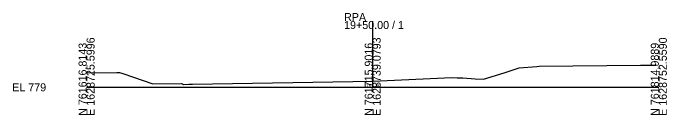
# Model space of a CAD drawing. Extents: x -26 to 203, y 990 to 7517.
# Drawn here: x -25.7 to 202.8, y 2990.3 to 3026 of the extents above; entities that cross this region are included whole.
import ezdxf

# ---------------------------------------------------------------- set-up
doc = ezdxf.new("R2010")
doc.units = 0
for name, color, linetype in [('Exist Cross Section Cell', 7, 'Continuous'), ('Exist XS Center Line Elevation Label', 7, 'Continuous'), ('Exist XS Ground Line', 7, 'Continuous')]:
    doc.layers.add(name, color=color, linetype=linetype)

msp = doc.modelspace()

# ---------------------------------------------------------------- linework, layer by layer
at = {"layer": 'Exist Cross Section Cell'}
for p, q in [((100, 3000), (100, 3023.24)), ((0, 3000), (100, 3000)), ((100, 3000), (200, 3000))]:
    msp.add_line(p, q, dxfattribs=at)
at = {"layer": 'Exist XS Ground Line'}
for p, q in [((158.14, 3007.41), (193.61, 3007.75)), ((193.61, 3007.75), (199.01, 3007.74)), ((199.01, 3007.74), (199.21, 3007.72)), ((145.96, 3005.04), (151.14, 3006.86)), ((151.14, 3006.86), (157.38, 3007.28)), ((157.38, 3007.28), (158.14, 3007.41)), ((0, 3005.12), (10.57, 3005.17)), ((10.57, 3005.17), (11.04, 3005.18)), ((11.04, 3005.18), (11.46, 3005.19)), ((11.46, 3005.19), (12.71, 3004.83)), ((12.71, 3004.83), (23.15, 3001.27)), ((100, 3002.2), (127.67, 3003.4)), ((127.67, 3003.4), (129.51, 3003.38)), ((129.51, 3003.38), (131.45, 3003.3)), ((131.45, 3003.3), (135.84, 3002.97)), ((135.84, 3002.97), (138.68, 3002.81)), ((138.68, 3002.81), (145.96, 3005.04)), ((23.15, 3001.27), (33.15, 3001.39)), ((33.15, 3001.39), (33.47, 3001.22)), ((33.47, 3001.22), (33.91, 3000.98)), ((33.91, 3000.98), (35.78, 3001.09)), ((35.78, 3001.09), (37.05, 3001.1)), ((37.05, 3001.1), (100, 3002.2))]:
    msp.add_line(p, q, dxfattribs=at)

# ---------------------------------------------------------------- texts
at = {"layer": 'Exist Cross Section Cell'}
for s, p in [('RPA', (90, 3023.24)), ('19+50.00 / 1', (90, 3020.44)), ('EL 779', (-26, 2998.6))]:
    msp.add_text(s, height=2.8, dxfattribs=at).set_placement(p)
for s, p in [('E 1628725.5996', (2.8, 2990)), ('E 1628739.0793', (102.8, 2990)), ('E 1628752.5590', (202.8, 2990)), ('N 761616.8143', (0, 2990)), ('N 761715.9016', (100, 2990)), ('N 761814.9889', (200, 2990))]:
    msp.add_text(s, height=2.8, rotation=90, dxfattribs=at).set_placement(p)
at = {"layer": 'Exist XS Center Line Elevation Label'}
msp.add_text('781.20', height=1.2, dxfattribs=at).set_placement((97.69, 3000))

doc.saveas('drawing.dxf')
